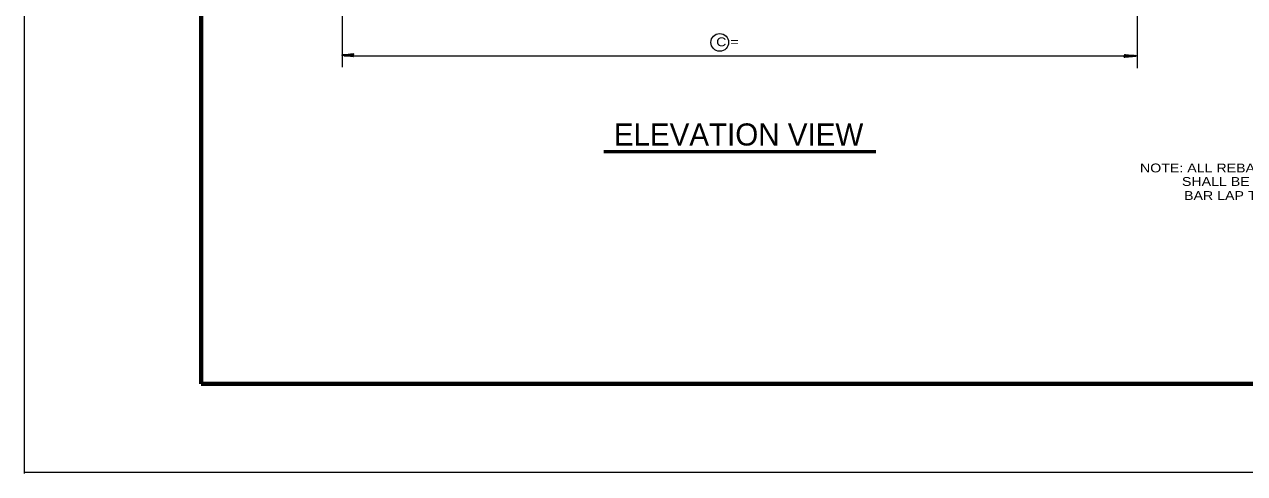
# Model space of a CAD drawing. Extents: x 6.34 to 9.53, y -1.46 to 0.53.
# Drawn here: x 6.336 to 7.487, y -1.46 to -1.036 of the extents above; entities that cross this region are included whole.
import ezdxf

# ---------------------------------------------------------------- set-up
doc = ezdxf.new("R2010")
doc.units = 0
doc.header["$LTSCALE"] = 0.0033
doc.layers.add('1', color=7, linetype='Continuous', lineweight=40)

msp = doc.modelspace()

# ---------------------------------------------------------------- linework, layer by layer
at = {"layer": '1', "lineweight": 13}
for p, q in [((6.336, -1.46), (6.336, 0.52825)), ((6.635583, -0.8165), (6.635583, -1.076917)), ((7.385583, -0.892917), (7.385583, -1.077833)), ((6.637667, -1.066083), (7.020667, -1.066083)), ((7.018833, -1.066083), (7.38425, -1.066083)), ((9.53275, -1.458833), (6.336, -1.458833))]:
    msp.add_line(p, q, dxfattribs=at)
at = {"layer": '1', "lineweight": 35}
for p, q in [((6.646333, -1.065583), (6.63575, -1.065583)), ((6.646083, -1.066417), (6.63825, -1.065417)), ((6.646083, -1.066417), (6.63825, -1.065583)), ((6.646083, -1.066583), (6.63825, -1.065667)), ((6.646083, -1.066583), (6.63825, -1.065667)), ((6.646083, -1.0665), (6.63825, -1.065667)), ((6.646083, -1.0645), (6.63875, -1.065333)), ((6.646083, -1.064667), (6.63875, -1.065417)), ((6.646083, -1.06475), (6.63875, -1.065583)), ((6.646167, -1.064917), (6.638833, -1.065667)), ((7.373667, -1.066083), (7.38425, -1.066083)), ((7.373833, -1.06675), (7.381167, -1.066)), ((7.373917, -1.065083), (7.38175, -1.066)), ((7.373917, -1.065083), (7.38175, -1.066)), ((7.373917, -1.065167), (7.38175, -1.066)), ((7.373917, -1.06525), (7.38175, -1.066083)), ((7.373917, -1.06525), (7.38175, -1.06625)), ((7.373917, -1.066917), (7.38125, -1.066083)), ((7.373917, -1.067), (7.38125, -1.06625)), ((7.373917, -1.067167), (7.38125, -1.066333))]:
    msp.add_line(p, q, dxfattribs=at)
at = {"layer": '1', "lineweight": 53}
msp.add_line((6.8825, -1.156417), (7.139, -1.156417), dxfattribs=at)
at = {"layer": '1', "lineweight": 70}
msp.add_line((6.50275, -1.3755), (9.449417, -1.3755), dxfattribs=at)
msp.add_lwpolyline([(9.449417, -1.3755), (9.449417, 0.444583), (6.50275, 0.444583), (6.50275, -1.3755)], dxfattribs=at)
at = {"layer": '1'}
msp.add_lwpolyline([(6.50275, -1.3755), (8.864417, -1.3755), (8.864417, -1.050417), (9.449417, -1.050417)], dxfattribs=at)
at = {"layer": '1', "lineweight": 35}
for points in [[(6.646333, -1.066667), (6.63575, -1.065583), (6.646333, -1.064417), (6.64575, -1.065583)], [(6.645583, -1.065667), (6.640917, -1.06575), (6.640917, -1.065667), (6.641833, -1.065667), (6.645583, -1.06575), (6.642583, -1.065833), (6.64575, -1.065917), (6.6435, -1.066), (6.64575, -1.066083), (6.64225, -1.065833), (6.637583, -1.065667), (6.6385, -1.065417), (6.63725, -1.065417), (6.645583, -1.065417), (6.643167, -1.06525), (6.64575, -1.06525), (6.640417, -1.065667), (6.64575, -1.065)], [(7.373667, -1.065), (7.38425, -1.066083), (7.373667, -1.06725), (7.37425, -1.066083)], [(7.374417, -1.066), (7.379083, -1.065917), (7.379083, -1.066), (7.378167, -1.066), (7.374417, -1.065917), (7.377417, -1.065833), (7.37425, -1.06575), (7.3765, -1.065667), (7.37425, -1.065583), (7.37775, -1.065833), (7.382417, -1.066), (7.3815, -1.06625), (7.38275, -1.06625), (7.374417, -1.06625), (7.376833, -1.066417), (7.37425, -1.066417), (7.379583, -1.066), (7.37425, -1.066667)]]:
    msp.add_lwpolyline(points, close=True, dxfattribs=at)
for points in [[(6.645583, -1.065667), (6.646, -1.066417), (6.64575, -1.066167), (6.645583, -1.065833), (6.645333, -1.065917), (6.6455, -1.06625), (6.645667, -1.0655), (6.645833, -1.065), (6.646083, -1.064583)], [(7.374417, -1.066), (7.374, -1.06525), (7.37425, -1.0655), (7.374417, -1.065833), (7.374667, -1.06575), (7.3745, -1.065417), (7.374333, -1.066167), (7.374167, -1.066667), (7.373917, -1.067083)]]:
    msp.add_lwpolyline(points, dxfattribs=at)
at = {"layer": '1', "lineweight": 13}
msp.add_circle((6.991833, -1.053417), 0.008333, dxfattribs=at)

# ---------------------------------------------------------------- texts
at = {"layer": '1', "width": 1.2}
for s, p in [('C =      ', (6.988417, -1.057083)), ('NOTE: ALL REBAR LAP SPLICES', (7.388167, -1.176)), ('SHALL BE AS PRESCRIBED IN', (7.42775, -1.18875)), ('BAR LAP TABLE', (7.42975, -1.202))]:
    msp.add_text(s, height=0.008334, dxfattribs=at).set_placement(p)
at = {"layer": '1'}
msp.add_text('ELEVATION VIEW', height=0.02083, dxfattribs=at).set_placement((6.891917, -1.150667))

doc.saveas('drawing.dxf')
